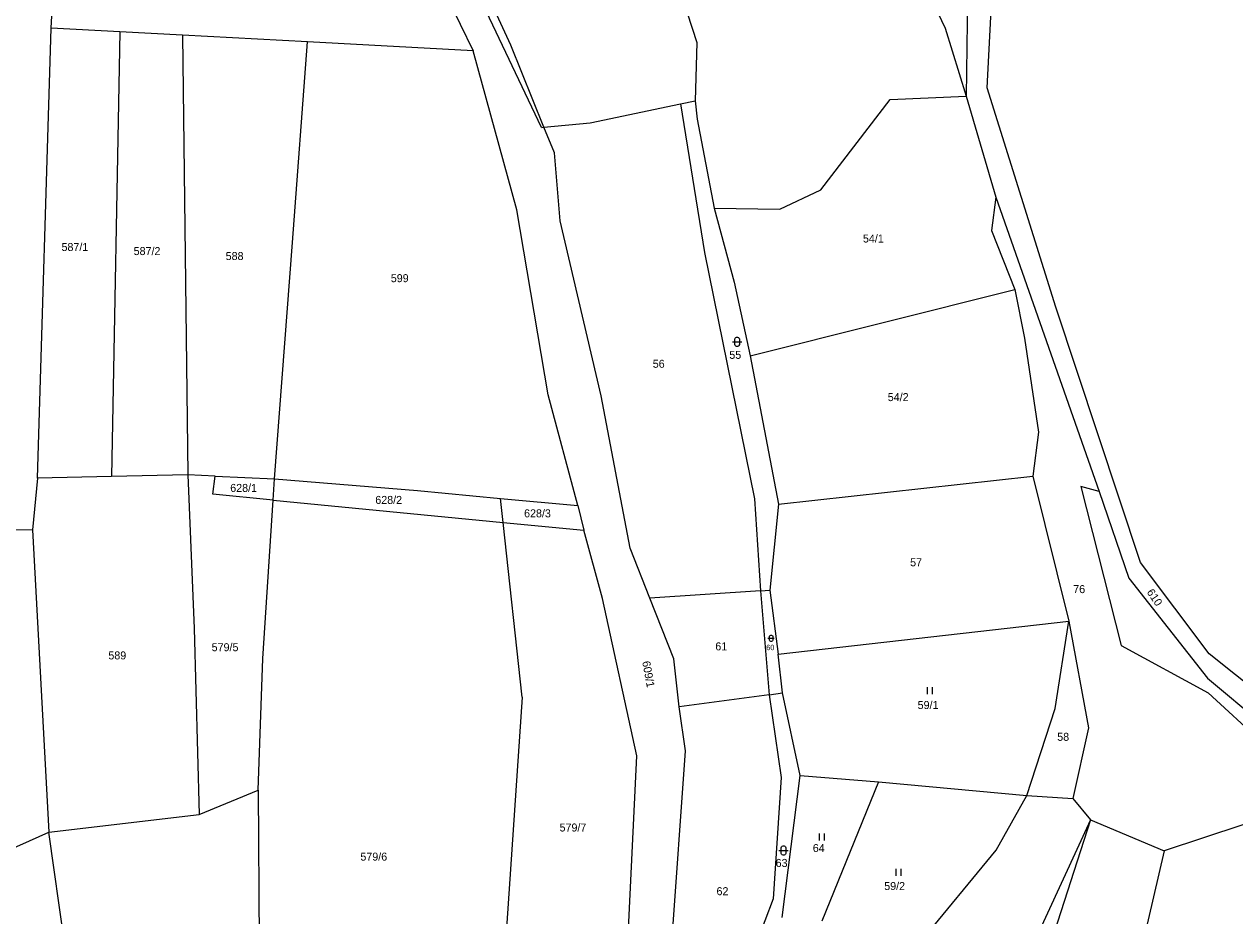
# Model space of a CAD drawing. Extents: x -794421 to -792735, y -1117671 to -1115559.
# Drawn here: x -793366.7 to -793109.5, y -1117244.8 to -1117055.3 of the extents above; entities that cross this region are included whole.
import ezdxf

# ---------------------------------------------------------------- set-up
doc = ezdxf.new("R2010")
doc.units = 0
for name, color, linetype in [('Vrstva 1', 7, 'Continuous'), ('Vrstva 14', 7, 'Continuous'), ('Vrstva 23', 7, 'Continuous')]:
    doc.layers.add(name, color=color, linetype=linetype)

msp = doc.modelspace()

# ---------------------------------------------------------------- linework, layer by layer
at = {"layer": 'Vrstva 1'}
for p, q in [((-793289.72, -1117022.82), (-793271.32, -1117060.97)), ((-793256.81, -1117077.23), (-793282.07, -1117023.71)), ((-793231.5, -1117035.41), (-793223.75, -1117059.17)), ((-793263.29, -1117059.75), (-793273.41, -1117037.8)), ((-793180.05, -1117037.18), (-793171.02, -1117056.17)), ((-793360.97, -1117056.14), (-793360.32, -1117044.13)), ((-793166.2, -1117043.88), (-793166.59, -1117070.61)), ((-793162.08, -1117068.82), (-793161.06, -1117048.89)), ((-793363.84, -1117151.77), (-793360.97, -1117056.14)), ((-793346.39, -1117056.92), (-793360.97, -1117056.14)), ((-793171.02, -1117056.17), (-793166.59, -1117070.61)), ((-793346.39, -1117056.92), (-793348.14, -1117151.43)), ((-793333.06, -1117057.64), (-793346.39, -1117056.92)), ((-793333.06, -1117057.64), (-793331.94, -1117151.08)), ((-793306.5, -1117059.07), (-793333.06, -1117057.64)), ((-793309.69, -1117101.66), (-793306.5, -1117059.07)), ((-793271.32, -1117060.97), (-793306.5, -1117059.07)), ((-793262, -1117094.76), (-793271.32, -1117060.97)), ((-793256.26, -1117077.16), (-793263.29, -1117059.75)), ((-793223.75, -1117059.17), (-793224.14, -1117071.58)), ((-793147.5, -1117115.4), (-793162.08, -1117068.82)), ((-793227.23, -1117072.25), (-793224.14, -1117071.58)), ((-793224.14, -1117071.58), (-793223.74, -1117075.49)), ((-793197.47, -1117090.47), (-793182.68, -1117071.29)), ((-793182.68, -1117071.29), (-793166.59, -1117070.61)), ((-793166.59, -1117070.61), (-793160.25, -1117092.03)), ((-793246.41, -1117076.27), (-793227.23, -1117072.25)), ((-793227.23, -1117072.25), (-793222.18, -1117103.83)), ((-793256.26, -1117077.16), (-793246.41, -1117076.27)), ((-793223.74, -1117075.49), (-793220.1, -1117094.36)), ((-793256.81, -1117077.23), (-793256.26, -1117077.16)), ((-793254.05, -1117082.65), (-793256.26, -1117077.16)), ((-793252.8, -1117097.05), (-793254.05, -1117082.65)), ((-793206.16, -1117094.64), (-793197.47, -1117090.47)), ((-793160.25, -1117092.03), (-793161.2, -1117099.15)), ((-793160.25, -1117092.03), (-793138.3, -1117154.59)), ((-793255.37, -1117134.05), (-793262, -1117094.76)), ((-793220.1, -1117094.36), (-793215.84, -1117110.14)), ((-793220.1, -1117094.36), (-793206.16, -1117094.64)), ((-793244.13, -1117134.29), (-793252.8, -1117097.05)), ((-793161.2, -1117099.15), (-793156.25, -1117111.71)), ((-793313.51, -1117151.92), (-793309.69, -1117101.66)), ((-793222.18, -1117103.83), (-793211.5, -1117156.14)), ((-793215.84, -1117110.14), (-793212.48, -1117125.76)), ((-793212.48, -1117125.76), (-793156.25, -1117111.71)), ((-793156.25, -1117111.71), (-793154.17, -1117121.99)), ((-793129.51, -1117169.71), (-793147.5, -1117115.4)), ((-793154.17, -1117121.99), (-793151.17, -1117141.97)), ((-793212.48, -1117125.76), (-793206.41, -1117157.32)), ((-793249.07, -1117157.6), (-793255.37, -1117134.05)), ((-793237.94, -1117166.63), (-793244.13, -1117134.29)), ((-793151.17, -1117141.97), (-793152.41, -1117151.32)), ((-793348.14, -1117151.43), (-793363.84, -1117151.77)), ((-793331.94, -1117151.08), (-793348.14, -1117151.43)), ((-793326.1, -1117151.35), (-793331.94, -1117151.08)), ((-793331.94, -1117151.08), (-793330.56, -1117183.69)), ((-793326.6, -1117155.16), (-793326.1, -1117151.35)), ((-793326.1, -1117151.35), (-793313.51, -1117151.92)), ((-793206.41, -1117157.32), (-793152.41, -1117151.32)), ((-793152.41, -1117151.32), (-793144.76, -1117182.13)), ((-793363.84, -1117151.77), (-793364.89, -1117162.78)), ((-793313.75, -1117156.41), (-793313.51, -1117151.92)), ((-793313.51, -1117151.92), (-793283.15, -1117154.42)), ((-793142.23, -1117153.56), (-793133.65, -1117187.29)), ((-793138.3, -1117154.59), (-793142.23, -1117153.56)), ((-793313.75, -1117156.41), (-793326.6, -1117155.16)), ((-793316.01, -1117190.11), (-793313.75, -1117156.41)), ((-793313.75, -1117156.41), (-793264.92, -1117161.18)), ((-793283.15, -1117154.42), (-793265.47, -1117156.07)), ((-793264.92, -1117161.18), (-793265.47, -1117156.07)), ((-793265.47, -1117156.07), (-793249.07, -1117157.6)), ((-793211.5, -1117156.14), (-793210.29, -1117175.71)), ((-793138.3, -1117154.59), (-793132.02, -1117173.04)), ((-793249.07, -1117157.6), (-793247.76, -1117162.85)), ((-793206.41, -1117157.32), (-793208.28, -1117175.56)), ((-793260.9, -1117198.31), (-793264.92, -1117161.18)), ((-793264.92, -1117161.18), (-793247.76, -1117162.85)), ((-793379.6, -1117162.41), (-793364.89, -1117162.78)), ((-793364.89, -1117162.78), (-793361.44, -1117226.97)), ((-793243.84, -1117177.35), (-793247.76, -1117162.85)), ((-793233.75, -1117177.24), (-793237.94, -1117166.63)), ((-793114.94, -1117189.09), (-793129.51, -1117169.71)), ((-793132.02, -1117173.04), (-793115.3, -1117194.27)), ((-793236.5, -1117210.76), (-793243.84, -1117177.35)), ((-793210.29, -1117175.71), (-793233.75, -1117177.24)), ((-793228.64, -1117190.15), (-793233.75, -1117177.24)), ((-793210.29, -1117175.71), (-793208.28, -1117175.56)), ((-793210.29, -1117175.71), (-793208.4, -1117197.79)), ((-793208.28, -1117175.56), (-793206.53, -1117189.16)), ((-793206.53, -1117189.16), (-793144.76, -1117182.13)), ((-793147.66, -1117200.68), (-793144.76, -1117182.13)), ((-793144.76, -1117182.13), (-793140.6, -1117204.79)), ((-793330.56, -1117183.69), (-793329.5, -1117223.22)), ((-793133.65, -1117187.29), (-793115.19, -1117197.4)), ((-793316.98, -1117218.04), (-793316.01, -1117190.11)), ((-793227.52, -1117200.36), (-793228.64, -1117190.15)), ((-793205.57, -1117197.38), (-793206.53, -1117189.16)), ((-793093.15, -1117206.52), (-793114.94, -1117189.09)), ((-793115.3, -1117194.27), (-793091.34, -1117214.31)), ((-793208.4, -1117197.79), (-793227.52, -1117200.36)), ((-793208.4, -1117197.79), (-793205.57, -1117197.38)), ((-793208.4, -1117197.79), (-793205.88, -1117215.4)), ((-793201.81, -1117214.94), (-793205.57, -1117197.38)), ((-793115.19, -1117197.4), (-793099.28, -1117212.02)), ((-793260.9, -1117198.31), (-793266.07, -1117275.47)), ((-793226.18, -1117209.72), (-793227.52, -1117200.36)), ((-793153.69, -1117219.23), (-793147.66, -1117200.68)), ((-793140.6, -1117204.79), (-793143.87, -1117219.85)), ((-793238.67, -1117254.97), (-793236.5, -1117210.76)), ((-793229.4, -1117254.52), (-793226.18, -1117209.72)), ((-793205.88, -1117215.4), (-793207.55, -1117241.17)), ((-793205.62, -1117245.12), (-793201.81, -1117214.94)), ((-793201.81, -1117214.94), (-793185.17, -1117216.32)), ((-793329.5, -1117223.22), (-793316.98, -1117218.04)), ((-793316.98, -1117218.04), (-793316.4, -1117300.84)), ((-793185.17, -1117216.32), (-793197.22, -1117245.93)), ((-793185.17, -1117216.32), (-793153.69, -1117219.23)), ((-793160.21, -1117230.85), (-793153.69, -1117219.23)), ((-793153.69, -1117219.23), (-793143.87, -1117219.85)), ((-793143.87, -1117219.85), (-793140.12, -1117224.4)), ((-793361.44, -1117226.97), (-793329.5, -1117223.22)), ((-793140.12, -1117224.4), (-793154.91, -1117256.34)), ((-793140.12, -1117224.4), (-793151.88, -1117260.51)), ((-793140.12, -1117224.4), (-793124.49, -1117230.97)), ((-793107.76, -1117225.41), (-793124.49, -1117230.97)), ((-793386.06, -1117238.09), (-793361.44, -1117226.97)), ((-793355.3, -1117270.13), (-793361.44, -1117226.97)), ((-793177.68, -1117252.02), (-793160.21, -1117230.85)), ((-793124.49, -1117230.97), (-793132.78, -1117266.28)), ((-793207.55, -1117241.17), (-793215.51, -1117262.2))]:
    msp.add_line(p, q, dxfattribs=at)
at = {"layer": 'Vrstva 23'}
for p, q in [((-793216.23, -1117122.79), (-793214.23, -1117122.79)), ((-793215.73, -1117122.19), (-793215.63, -1117121.99)), ((-793215.73, -1117123.39), (-793215.73, -1117122.19)), ((-793215.63, -1117121.99), (-793215.53, -1117121.89)), ((-793215.53, -1117121.89), (-793215.33, -1117121.79)), ((-793215.33, -1117121.79), (-793215.13, -1117121.79)), ((-793215.13, -1117121.79), (-793214.93, -1117121.89)), ((-793214.93, -1117121.89), (-793214.83, -1117121.99)), ((-793214.83, -1117121.99), (-793214.73, -1117122.19)), ((-793214.73, -1117122.19), (-793214.73, -1117123.39)), ((-793215.63, -1117123.59), (-793215.73, -1117123.39)), ((-793215.53, -1117123.69), (-793215.63, -1117123.59)), ((-793215.33, -1117123.79), (-793215.53, -1117123.69)), ((-793215.13, -1117123.79), (-793215.33, -1117123.79)), ((-793214.93, -1117123.69), (-793215.13, -1117123.79)), ((-793214.83, -1117123.59), (-793214.93, -1117123.69)), ((-793214.73, -1117123.39), (-793214.83, -1117123.59)), ((-793208.67, -1117185.77), (-793207.33, -1117185.77)), ((-793208.335, -1117185.368), (-793208.268, -1117185.234)), ((-793208.335, -1117186.172), (-793208.335, -1117185.368)), ((-793208.268, -1117186.306), (-793208.335, -1117186.172)), ((-793208.268, -1117185.234), (-793208.201, -1117185.167)), ((-793208.201, -1117186.373), (-793208.268, -1117186.306)), ((-793208.201, -1117185.167), (-793208.067, -1117185.1)), ((-793208.067, -1117186.44), (-793208.201, -1117186.373)), ((-793208.067, -1117185.1), (-793207.933, -1117185.1)), ((-793207.933, -1117186.44), (-793208.067, -1117186.44)), ((-793207.933, -1117185.1), (-793207.799, -1117185.167)), ((-793207.799, -1117186.373), (-793207.933, -1117186.44)), ((-793207.799, -1117185.167), (-793207.732, -1117185.234)), ((-793207.732, -1117186.306), (-793207.799, -1117186.373)), ((-793207.732, -1117185.234), (-793207.665, -1117185.368)), ((-793207.665, -1117186.172), (-793207.732, -1117186.306)), ((-793207.665, -1117185.368), (-793207.665, -1117186.172)), ((-793174.77, -1117197.67), (-793174.77, -1117196.17)), ((-793173.77, -1117196.17), (-793173.77, -1117197.67)), ((-793197.75, -1117228.76), (-793197.75, -1117227.26)), ((-793196.75, -1117227.26), (-793196.75, -1117228.76)), ((-793206.36, -1117230.9), (-793204.36, -1117230.9)), ((-793205.86, -1117230.3), (-793205.76, -1117230.1)), ((-793205.86, -1117231.5), (-793205.86, -1117230.3)), ((-793205.76, -1117230.1), (-793205.66, -1117230)), ((-793205.66, -1117230), (-793205.46, -1117229.9)), ((-793205.46, -1117229.9), (-793205.26, -1117229.9)), ((-793205.26, -1117229.9), (-793205.06, -1117230)), ((-793205.06, -1117230), (-793204.96, -1117230.1)), ((-793204.96, -1117230.1), (-793204.86, -1117230.3)), ((-793204.86, -1117230.3), (-793204.86, -1117231.5)), ((-793205.76, -1117231.7), (-793205.86, -1117231.5)), ((-793205.66, -1117231.8), (-793205.76, -1117231.7)), ((-793205.46, -1117231.9), (-793205.66, -1117231.8)), ((-793205.26, -1117231.9), (-793205.46, -1117231.9)), ((-793205.06, -1117231.8), (-793205.26, -1117231.9)), ((-793204.96, -1117231.7), (-793205.06, -1117231.8)), ((-793204.86, -1117231.5), (-793204.96, -1117231.7)), ((-793181.44, -1117236.27), (-793181.44, -1117234.77)), ((-793180.44, -1117234.77), (-793180.44, -1117236.27))]:
    msp.add_line(p, q, dxfattribs=at)

# ---------------------------------------------------------------- texts
at = {"layer": 'Vrstva 14'}
for s, height, p in [('54/1', 1.7, (-793188.495, -1117101.69)), ('587/1', 1.7, (-793358.746, -1117103.5)), ('587/2', 1.7, (-793343.422, -1117104.36)), ('588', 1.7, (-793323.873, -1117105.42)), ('599', 1.7, (-793288.793, -1117110.12)), ('55', 1.7, (-793216.879, -1117126.41)), ('56', 1.7, (-793233.143, -1117128.31)), ('54/2', 1.7, (-793183.222, -1117135.39)), ('628/1', 1.7, (-793322.903, -1117154.69)), ('628/2', 1.7, (-793292.089, -1117157.24)), ('628/3', 1.7, (-793260.48, -1117160.09)), ('57', 1.7, (-793178.47, -1117170.49)), ('76', 1.7, (-793143.823, -1117176.19)), ('579/5', 1.7, (-793326.849, -1117188.54)), ('61', 1.7, (-793219.85, -1117188.36)), ('60', 1.14, (-793209.053, -1117188.31)), ('589', 1.7, (-793348.793, -1117190.28)), ('59/1', 1.7, (-793176.87, -1117200.82)), ('58', 1.7, (-793147.223, -1117207.58)), ('579/7', 1.7, (-793252.939, -1117226.85)), ('579/6', 1.7, (-793295.253, -1117233.04)), ('64', 1.7, (-793199.143, -1117231.21)), ('63', 1.7, (-793207.037, -1117234.38)), ('62', 1.7, (-793219.597, -1117240.39)), ('59/2', 1.7, (-793183.976, -1117239.29))]:
    msp.add_text(s, height=height, dxfattribs=at).set_placement(p)
for s, rotation, p in [('610', 303.9912, (-793128.286, -1117175.998)), ('609/1', 280.52766, (-793235.398, -1117190.782))]:
    msp.add_text(s, height=1.7, rotation=rotation, dxfattribs=at).set_placement(p)

doc.saveas('drawing.dxf')
